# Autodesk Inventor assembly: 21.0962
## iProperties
Created: 2011-07
Part Number: 21.0962
Document SubType Name: Assembly
Designer: Administrator
Description: PROFILE HANDLE 32
Mass: 488.828 g
Surface Area: 1152.06 cm^2
Volume: 155.699 cm^3
Density: 3.13958 g/cm^3
Author: Administrator
